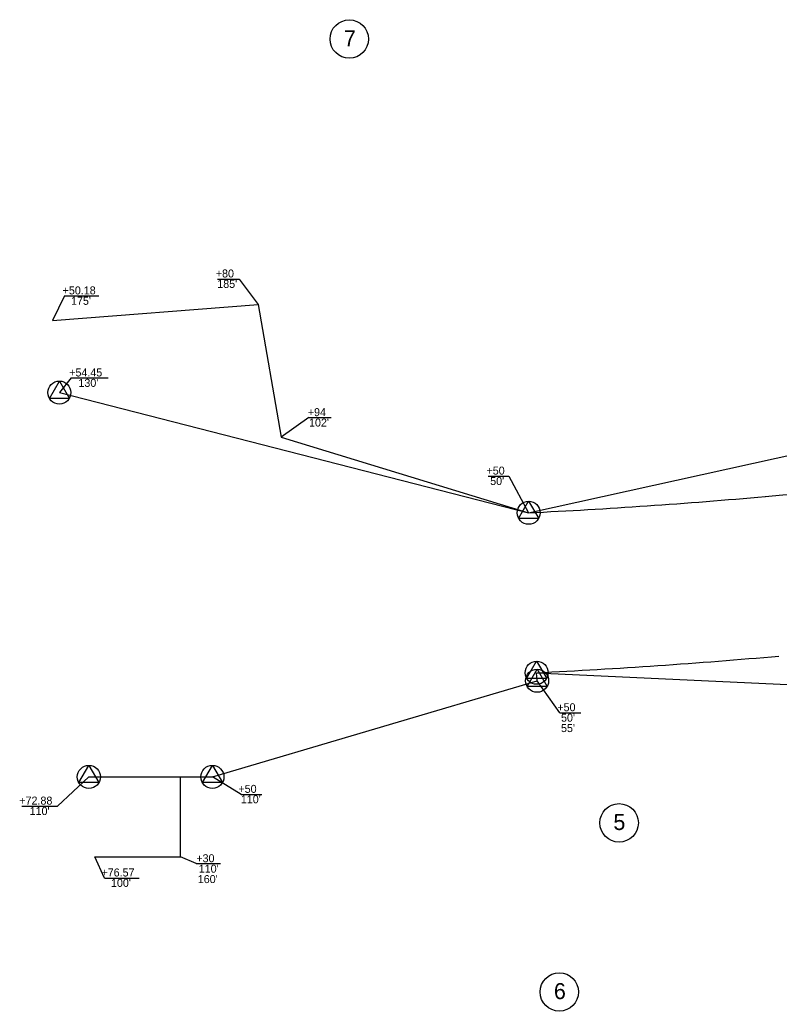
# Model space of a CAD drawing. Extents: x 1618217 to 1621927, y 897445 to 899141.
# Drawn here: x 1620057 to 1620531, y 897785 to 898404 of the extents above; entities that cross this region are included whole.
import ezdxf

# ---------------------------------------------------------------- set-up
doc = ezdxf.new("R2010")
doc.units = 0
for name, color, linetype in [('Prop Easement Construction', 7, 'Continuous'), ('Prop Easement Temporary Drainage', 7, 'Continuous'), ('Prop Easement Temporary Drainage Station Offsets', 7, 'Continuous'), ('Prop Parcel Number CELL', 7, 'Continuous'), ('Prop ROW Marker CELL', 7, 'Continuous'), ('Prop ROW RW Lines', 7, 'Continuous'), ('Prop ROW Station Offsets', 7, 'Continuous')]:
    doc.layers.add(name, color=color, linetype=linetype)

msp = doc.modelspace()

# ---------------------------------------------------------------- linework, layer by layer
at = {"layer": 'Prop Easement Construction'}
for p, q in [((1620374.41, 898096.16), (1620741.24, 898177.16)), ((1620379.4, 897996.28), (1620617.78, 897985.08))]:
    msp.add_line(p, q, dxfattribs=at)
at = {"layer": 'Prop Easement Temporary Drainage'}
for p, q in [((1620077.16, 898216.24), (1620205.62, 898226.34)), ((1620205.62, 898226.34), (1620219.87, 898143.47)), ((1620219.87, 898143.47), (1620374.41, 898096.16)), ((1620156.99, 897881.24), (1620156.99, 897931.24)), ((1620103.56, 897881.24), (1620156.99, 897881.24))]:
    msp.add_line(p, q, dxfattribs=at)
at = {"layer": 'Prop Easement Temporary Drainage Station Offsets'}
for p, q in [((1620180.07, 898242.15), (1620193.61, 898242.15)), ((1620193.61, 898242.15), (1620205.62, 898226.34)), ((1620084.71, 898231.69), (1620077.16, 898216.24)), ((1620084.71, 898231.69), (1620106.1, 898231.69)), ((1620237.09, 898155.68), (1620219.87, 898143.47)), ((1620237.09, 898155.68), (1620251.03, 898155.68)), ((1620109.66, 897867.92), (1620103.56, 897881.24)), ((1620166.92, 897877.05), (1620156.99, 897881.24)), ((1620166.92, 897877.05), (1620182.11, 897877.05)), ((1620109.66, 897867.92), (1620131.36, 897867.92))]:
    msp.add_line(p, q, dxfattribs=at)
at = {"layer": 'Prop Parcel Number CELL'}
for p, q in [((1620262.42, 898392.03), (1620262.42, 898392.03)), ((1620430.88, 897902.52), (1620430.88, 897902.52)), ((1620393.52, 897796.91), (1620393.52, 897796.91))]:
    msp.add_line(p, q, dxfattribs=at)
for centre in [(1620262.42, 898392.03), (1620430.88, 897902.52), (1620393.52, 897796.91)]:
    msp.add_circle(centre, 12, dxfattribs=at)
at = {"layer": 'Prop ROW Marker CELL'}
for p, q in [((1620081.44, 898171.24), (1620081.44, 898171.24)), ((1620374.41, 898096.16), (1620374.41, 898096.16)), ((1620379.4, 897996.28), (1620379.4, 897996.28)), ((1620379.65, 897991.29), (1620379.65, 897991.29)), ((1620099.86, 897931.24), (1620099.86, 897931.24)), ((1620176.99, 897931.24), (1620176.99, 897931.24))]:
    msp.add_line(p, q, dxfattribs=at)
for points in [[(1620075.19, 898167.64), (1620081.44, 898178.44), (1620087.69, 898167.64)], [(1620368.16, 898092.56), (1620374.41, 898103.36), (1620380.66, 898092.56)], [(1620373.15, 897992.68), (1620379.4, 898003.48), (1620385.65, 897992.68)], [(1620373.4, 897987.69), (1620379.65, 897998.49), (1620385.9, 897987.69)], [(1620093.61, 897927.64), (1620099.86, 897938.44), (1620106.11, 897927.64)], [(1620170.74, 897927.64), (1620176.99, 897938.44), (1620183.24, 897927.64)]]:
    msp.add_lwpolyline(points, close=True, dxfattribs=at)
for centre in [(1620081.44, 898171.24), (1620374.41, 898096.16), (1620379.4, 897996.28), (1620379.65, 897991.29), (1620099.86, 897931.24), (1620176.99, 897931.24)]:
    msp.add_circle(centre, 7.2, dxfattribs=at)
at = {"layer": 'Prop ROW RW Lines'}
for p, q in [((1620081.44, 898171.24), (1620374.41, 898096.16)), ((1620379.65, 897991.29), (1620379.4, 897996.28)), ((1620176.99, 897931.24), (1620379.65, 897991.29)), ((1620099.86, 897931.24), (1620176.99, 897931.24))]:
    msp.add_line(p, q, dxfattribs=at)
for radius, start, end in [(3950, 275.00553, 280.16405), (3950, 272.85884, 275.00743), (4050, 272.85884, 275.00403)]:
    msp.add_arc((1620177.4, 902041.24), radius, start, end, dxfattribs=at)
at = {"layer": 'Prop ROW Station Offsets'}
for p, q in [((1620088.79, 898180.45), (1620081.44, 898171.24)), ((1620088.79, 898180.45), (1620111.82, 898180.45)), ((1620349.12, 898119), (1620361.97, 898119)), ((1620361.97, 898119), (1620374.41, 898096.16)), ((1620393.87, 897971.29), (1620379.65, 897991.29)), ((1620393.87, 897971.29), (1620407, 897971.29)), ((1620080.21, 897912.98), (1620099.86, 897931.24)), ((1620194.93, 897920.29), (1620176.99, 897931.24)), ((1620194.93, 897920.29), (1620207.86, 897920.29)), ((1620058.03, 897912.98), (1620080.21, 897912.98))]:
    msp.add_line(p, q, dxfattribs=at)

# ---------------------------------------------------------------- texts
at = {"layer": 'Prop Easement Temporary Drainage Station Offsets'}
for s, p in [('+80', (1620179.1, 898243.12)), ('+50.18', (1620083.48, 898232.55)), ("185'", (1620180.01, 898236.62)), ("175'", (1620088.73, 898226.05)), ('+94', (1620236.54, 898156.51)), ("102'", (1620237.3, 898150.01)), ('+30', (1620166.95, 897877.91)), ('+76.57', (1620107.72, 897869.02)), ("110'", (1620168.46, 897871.41)), ("100'", (1620113.68, 897862.52)), ("160'", (1620167.86, 897864.91))]:
    msp.add_text(s, height=5, rotation=360, dxfattribs=at).set_placement(p)
at = {"layer": 'Prop Parcel Number CELL'}
for s, p in [('7', (1620259.1, 898387.56)), ('5', (1620427.33, 897898.05)), ('6', (1620390.17, 897792.44))]:
    msp.add_text(s, height=10, dxfattribs=at).set_placement(p)
at = {"layer": 'Prop ROW Station Offsets'}
for s, p in [('+54.45', (1620087.59, 898181.3)), ("130'", (1620093.34, 898174.8)), ('+50', (1620348.09, 898120.01)), ("50'", (1620350.38, 898113.51)), ('+50', (1620392.32, 897972.21)), ("50'", (1620394.61, 897965.71)), ("55'", (1620394.61, 897959.21)), ('+50', (1620193.23, 897921.25)), ('+72.88', (1620056.44, 897913.92)), ("110'", (1620194.73, 897914.75)), ("110'", (1620062.89, 897907.42))]:
    msp.add_text(s, height=5, rotation=360, dxfattribs=at).set_placement(p)

doc.saveas('drawing.dxf')
